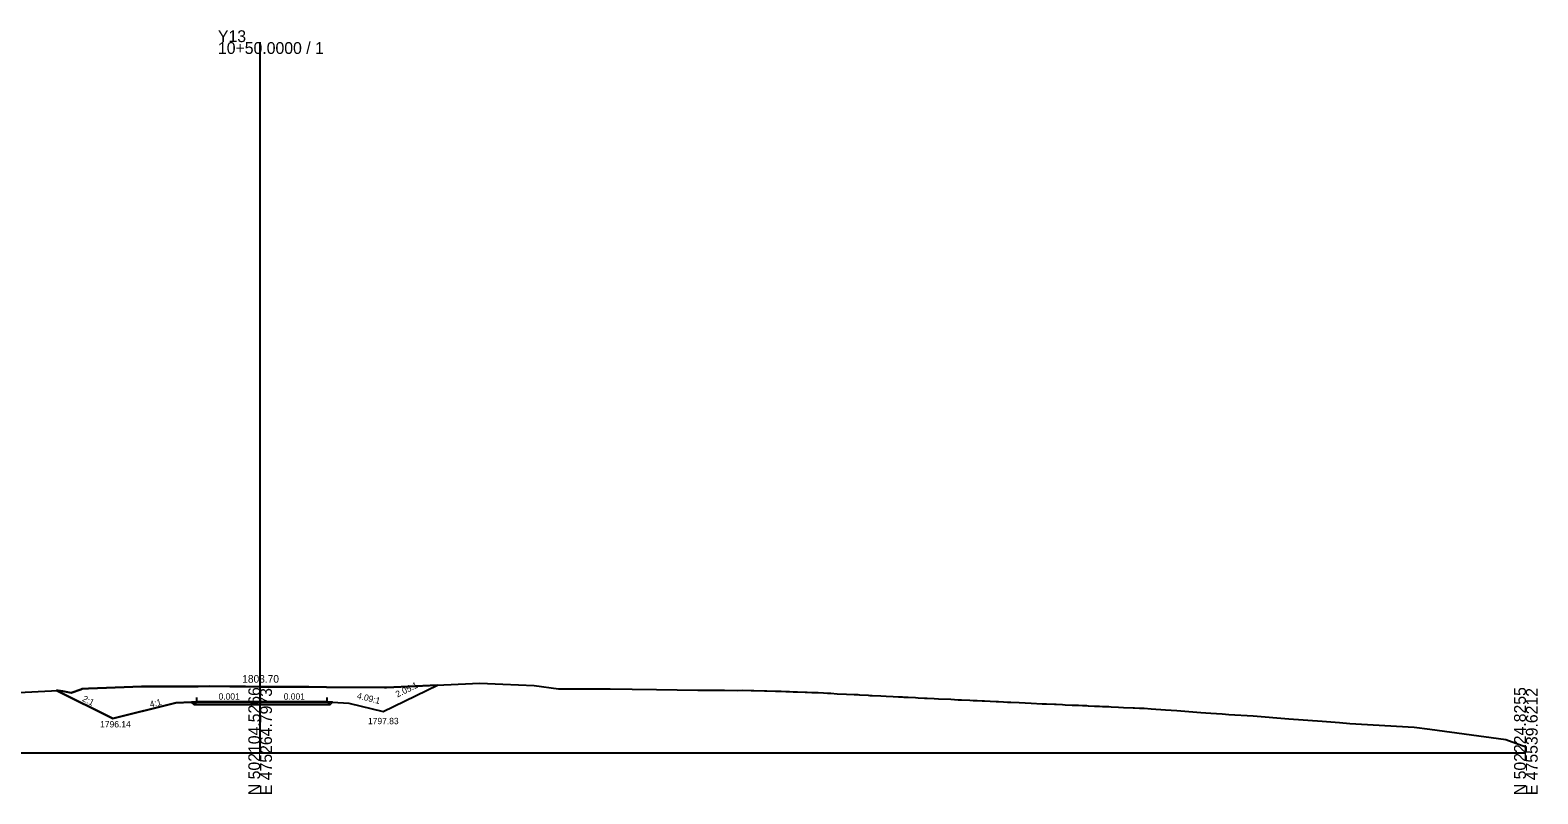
# Model space of a CAD drawing. Extents: x -126 to 503, y -10 to 2750.
# Drawn here: x 145.5 to 502.8, y 490.3 to 671.4 of the extents above; entities that cross this region are included whole.
import ezdxf

# ---------------------------------------------------------------- set-up
doc = ezdxf.new("R2010")
doc.units = 0
for name, color, linetype in [('Exist Cross Section Cell', 7, 'Continuous'), ('Exist XS Center Line Elevation Label', 7, 'Continuous'), ('Exist XS Ground Line', 7, 'Continuous'), ('Prop XS Ditch Slope Text', 7, 'Continuous'), ('Prop XS Ditch Standard Text', 7, 'Continuous'), ('Prop XS Dump Level', 7, 'Continuous'), ('Prop XS Earthwork Shape', 7, 'Continuous'), ('Prop XS EOT Tick Mark', 7, 'Continuous'), ('Prop XS Finish Grade', 7, 'Continuous'), ('Prop XS Finish Grade Earthwork', 7, 'Continuous'), ('Prop XS Finish Grade Pavement', 7, 'Continuous'), ('Prop XS Hydro Typical Ditch Data', 7, 'Continuous'), ('Prop XS Pvmt Edge Slope', 7, 'Continuous'), ('Prop XS SE Text', 7, 'Continuous'), ('Prop XS Shoulder Borrow Shape', 7, 'Continuous'), ('Prop XS Side Slope Text', 7, 'Continuous'), ('Prop XS Subgrade Earthwork', 7, 'Continuous')]:
    doc.layers.add(name, color=color, linetype=linetype)

msp = doc.modelspace()

# ---------------------------------------------------------------- linework, layer by layer
at = {"layer": 'Exist Cross Section Cell'}
for p, q in [((200, 500), (200, 668.57)), ((-100, 500), (200, 500)), ((200, 500), (500, 500))]:
    msp.add_line(p, q, dxfattribs=at)
at = {"layer": 'Exist XS Ground Line'}
msp.add_lwpolyline([(141.11, 514.28), (152.14, 514.82), (153.22, 514.65), (155.24, 514.3), (157.51, 515.08), (157.82, 515.22), (159.31, 515.3), (163.61, 515.47), (169.82, 515.68), (171.85, 515.8), (179.83, 515.77), (183.9, 515.79), (185.34, 515.79), (188.1, 515.81), (192.81, 515.75), (196.53, 515.73), (200, 515.7), (201.41, 515.69), (203.86, 515.68), (209.14, 515.69), (209.81, 515.69), (211.52, 515.7), (215.75, 515.58), (229.5, 515.49), (229.92, 515.52), (252.1, 516.58), (257.54, 516.32), (264.91, 516.01), (270.75, 515.25), (283, 515.18), (288.18, 515.12), (293.95, 515.05), (303.76, 514.92), (304.71, 514.91), (305.8, 514.89), (310.03, 514.87), (313.19, 514.84), (314.36, 514.88), (316.42, 514.83), (317.01, 514.82), (319.51, 514.75), (320.09, 514.74), (322.17, 514.67), (323.46, 514.63), (324.6, 514.6), (325.5, 514.55), (326.35, 514.54), (327.39, 514.5), (329.2, 514.43), (329.62, 514.42), (330.8, 514.37), (332.24, 514.31), (333.49, 514.25), (334.5, 514.2), (335.27, 514.15), (336.8, 514.06), (338.95, 513.95), (340.81, 513.88), (341.67, 513.83), (342.08, 513.81), (344.1, 513.68), (344.5, 513.66), (345.03, 513.63), (347.14, 513.53), (348.4, 513.49), (350.04, 513.4), (351.27, 513.33), (352.19, 513.28), (352.59, 513.26), (353.62, 513.21), (355.32, 513.14), (355.95, 513.11), (357.49, 513.02), (358.06, 512.99), (359.78, 512.91), (360.78, 512.87), (363.72, 512.73), (365.48, 512.64), (366.24, 512.6), (368.18, 512.51), (368.97, 512.47), (369.27, 512.46), (369.97, 512.42), (371.17, 512.36), (371.7, 512.33), (373.05, 512.27), (374.43, 512.2), (374.97, 512.18), (376.2, 512.12), (377.16, 512.07), (377.89, 512.04), (379.88, 511.94), (382.75, 511.81), (385.34, 511.69), (386.35, 511.66), (388.25, 511.56), (388.67, 511.54), (390.15, 511.48), (390.79, 511.45), (392.45, 511.37), (393.53, 511.33), (393.95, 511.31), (394.91, 511.28), (395.85, 511.24), (396.26, 511.22), (397.75, 511.14), (398.98, 511.1), (399.65, 511.06), (401.17, 511), (401.72, 510.97), (403.47, 510.87), (404.65, 510.82), (406.94, 510.72), (407.25, 510.7), (408.45, 510.64), (409.5, 510.59), (411.22, 510.48), (414.61, 510.24), (417.26, 510.05), (422.94, 509.63), (425.36, 509.46), (428.04, 509.26), (429.57, 509.13), (435.39, 508.78), (443.78, 508.06), (451.74, 507.57), (455.86, 507.22), (458.26, 507), (473.5, 506.12), (477.21, 505.65), (495.29, 503.19), (500, 501.44)], dxfattribs=at)
at = {"layer": 'Prop XS Dump Level'}
for p, q in [((200, 512.15), (185, 512.16)), ((215.87, 512.13), (200, 512.15))]:
    msp.add_line(p, q, dxfattribs=at)
at = {"layer": 'Prop XS Earthwork Shape'}
msp.add_lwpolyline([(220.99, 511.83), (229.17, 509.83), (242.01, 516.1), (229.92, 515.52), (229.5, 515.49), (215.75, 515.58), (211.52, 515.7), (209.81, 515.69), (209.14, 515.69), (203.86, 515.68), (201.41, 515.69), (200, 515.7), (196.53, 515.73), (192.81, 515.75), (188.1, 515.81), (185.34, 515.79), (183.9, 515.79), (179.83, 515.77), (171.85, 515.8), (169.82, 515.68), (163.61, 515.47), (159.31, 515.3), (157.82, 515.22), (157.51, 515.08), (155.24, 514.3), (153.22, 514.65), (152.14, 514.82), (151.77, 514.8), (165.1, 508.14), (180, 511.87), (183.74, 512.09), (184.33, 511.49), (185, 511.49), (200, 511.48), (215.87, 511.46), (216.56, 511.46), (217.16, 512.05)], close=True, dxfattribs=at)
at = {"layer": 'Prop XS EOT Tick Mark'}
for p, q in [((185, 512.16), (185, 513.16)), ((215.87, 512.13), (215.87, 513.13))]:
    msp.add_line(p, q, dxfattribs=at)
at = {"layer": 'Prop XS Finish Grade'}
for p, q in [((185, 512.16), (183.74, 512.09)), ((215.87, 512.13), (217.16, 512.05))]:
    msp.add_line(p, q, dxfattribs=at)
at = {"layer": 'Prop XS Finish Grade Earthwork'}
for p, q in [((165.1, 508.14), (151.77, 514.8)), ((229.17, 509.83), (242.01, 516.1)), ((180, 511.87), (165.1, 508.14)), ((183.74, 512.09), (180, 511.87)), ((217.16, 512.05), (220.99, 511.83)), ((220.99, 511.83), (229.17, 509.83))]:
    msp.add_line(p, q, dxfattribs=at)
at = {"layer": 'Prop XS Finish Grade Pavement'}
for p, q in [((185, 512.16), (200, 512.15)), ((200, 512.15), (215.87, 512.13))]:
    msp.add_line(p, q, dxfattribs=at)
at = {"layer": 'Prop XS Hydro Typical Ditch Data'}
for p, q in [((165.1, 508.14), (151.77, 514.8)), ((229.17, 509.83), (242.01, 516.1)), ((180, 511.87), (172, 509.87)), ((220.99, 511.83), (229.17, 509.83))]:
    msp.add_line(p, q, dxfattribs=at)
at = {"layer": 'Prop XS Pvmt Edge Slope'}
for p, q in [((185, 512.16), (184.33, 511.49)), ((215.87, 512.13), (216.56, 511.46))]:
    msp.add_line(p, q, dxfattribs=at)
at = {"layer": 'Prop XS Shoulder Borrow Shape'}
for points in [[(185, 512.16), (184.33, 511.49), (183.74, 512.09)], [(216.56, 511.46), (217.16, 512.05), (215.87, 512.13)]]:
    msp.add_lwpolyline(points, close=True, dxfattribs=at)
at = {"layer": 'Prop XS Subgrade Earthwork'}
for p, q in [((184.33, 511.49), (183.74, 512.09)), ((185, 511.49), (184.33, 511.49)), ((200, 511.48), (185, 511.49)), ((215.87, 511.46), (200, 511.48)), ((215.87, 511.46), (216.56, 511.46)), ((216.56, 511.46), (217.16, 512.05))]:
    msp.add_line(p, q, dxfattribs=at)

# ---------------------------------------------------------------- texts
at = {"layer": 'Exist Cross Section Cell'}
for s, p in [('Y13', (190, 668.57)), ('10+50.0000 / 1', (190, 665.77))]:
    msp.add_text(s, height=2.8, dxfattribs=at).set_placement(p)
for s, p in [('N 502104.5266', (200, 490)), ('E 475264.7973', (202.8, 490)), ('N 502224.8255', (500, 490)), ('E 475539.6212', (502.8, 490))]:
    msp.add_text(s, height=2.8, rotation=90, dxfattribs=at).set_placement(p)
at = {"layer": 'Exist XS Center Line Elevation Label'}
msp.add_text('1803.70', height=1.8, dxfattribs=at).set_placement((195.76, 516.67))
at = {"layer": 'Prop XS Ditch Slope Text'}
for s, rotation, p in [('4:1', 14.0362, (174.03, 510.76)), ('4.09:1', 346.2664, (222.84, 512.92))]:
    msp.add_text(s, height=1.5, rotation=rotation, dxfattribs=at).set_placement(p)
at = {"layer": 'Prop XS Ditch Standard Text'}
for s, p in [('1796.14', (162.08, 506.06)), ('1797.83', (225.57, 506.83))]:
    msp.add_text(s, height=1.5, dxfattribs=at).set_placement(p)
at = {"layer": 'Prop XS Dump Level'}
for p in [(180, 511.83), (220.99, 511.79)]:
    msp.add_text('Case1', height=0.04, dxfattribs=at).set_placement(p)
at = {"layer": 'Prop XS SE Text'}
for p in [(190.15, 512.66), (205.59, 512.64)]:
    msp.add_text('0.001', height=1.5, rotation=359.9426, dxfattribs=at).set_placement(p)
at = {"layer": 'Prop XS Side Slope Text'}
for s, rotation, p in [('2.05:1', 26.0489, (232.53, 513.14)), ('2:1', 333.4349, (157.71, 512.39))]:
    msp.add_text(s, height=1.5, rotation=rotation, dxfattribs=at).set_placement(p)

doc.saveas('drawing.dxf')
